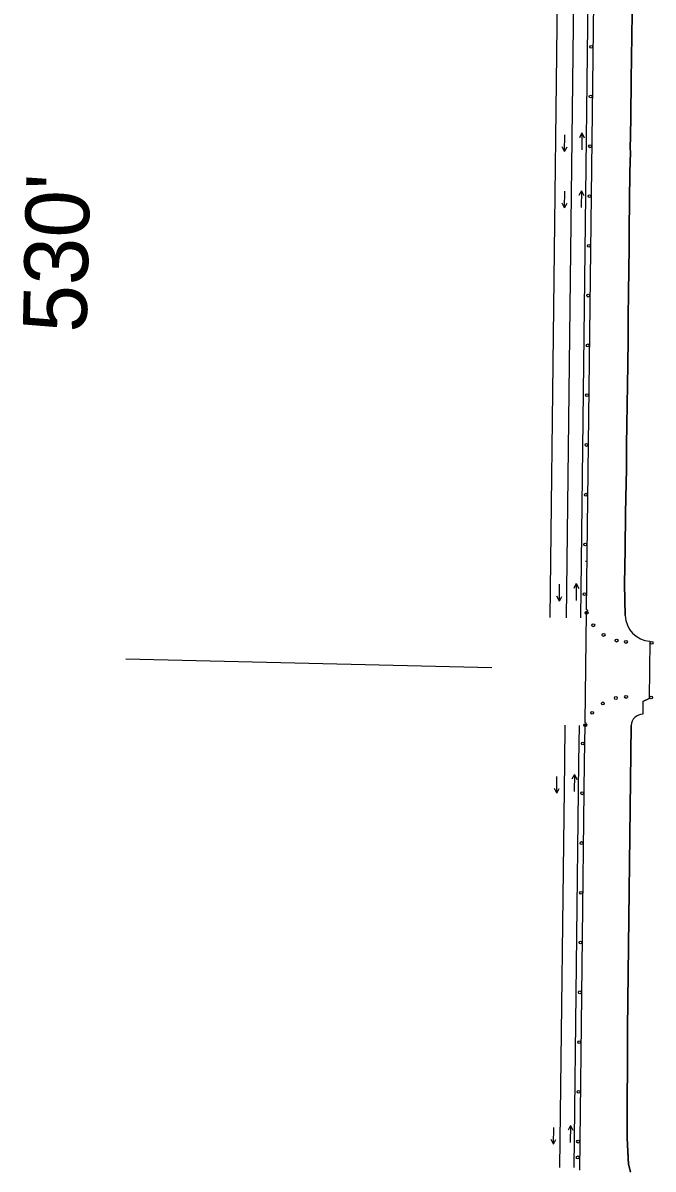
# Model space of a CAD drawing. Extents: x 1650647 to 1653016, y 602856 to 611467.
# Drawn here: x 1652157 to 1652600, y 606913 to 607719 of the extents above; entities that cross this region are included whole.
import ezdxf

# ---------------------------------------------------------------- set-up
doc = ezdxf.new("R2010")
doc.units = 0
for name, color, linetype in [('CM_Corridor_Design', 7, 'Continuous'), ('DT_X_Break_Line', 7, 'Continuous'), ('DT_X_Contour_Major', 7, 'Continuous'), ('PV_P_EOP', 7, 'Continuous'), ('PV_X_EOP', 7, 'Continuous'), ('SC_Scratch1', 7, 'Continuous'), ('UT_X_Water', 7, 'Continuous')]:
    doc.layers.add(name, color=color, linetype=linetype)

msp = doc.modelspace()

# ---------------------------------------------------------------- linework, layer by layer
at = {"layer": 'CM_Corridor_Design'}
for p, q in [((1652549.84, 607641.96), (1652548.08, 607638.6)), ((1652549.84, 607641.96), (1652549.71, 607630.1)), ((1652549.84, 607641.96), (1652551.52, 607638.57)), ((1652537.69, 607628.82), (1652537.82, 607640.68)), ((1652537.69, 607628.82), (1652536.01, 607632.22)), ((1652537.69, 607628.82), (1652539.45, 607632.18)), ((1652549.54, 607601.28), (1652547.78, 607597.92)), ((1652549.54, 607601.28), (1652549.41, 607589.42)), ((1652549.54, 607601.28), (1652551.23, 607597.89)), ((1652537.66, 607589.19), (1652537.79, 607601.05)), ((1652537.66, 607589.19), (1652535.97, 607592.59)), ((1652537.66, 607589.19), (1652539.42, 607592.55)), ((1652533.98, 607312.71), (1652534.11, 607324.57)), ((1652545.91, 607325.03), (1652544.15, 607321.68)), ((1652545.91, 607325.03), (1652545.78, 607313.18)), ((1652545.91, 607325.03), (1652547.6, 607321.64)), ((1652533.98, 607312.71), (1652532.29, 607316.1)), ((1652533.98, 607312.71), (1652535.74, 607316.07)), ((1652544.59, 607190.75), (1652542.83, 607187.4)), ((1652544.59, 607190.75), (1652544.46, 607178.9)), ((1652544.59, 607190.75), (1652546.27, 607187.36)), ((1652532.12, 607177.57), (1652532.25, 607189.43)), ((1652532.12, 607177.57), (1652530.44, 607180.96)), ((1652532.12, 607177.57), (1652533.88, 607180.93)), ((1652529.84, 606930.77), (1652529.97, 606942.63)), ((1652541.82, 606943.94), (1652540.06, 606940.59)), ((1652541.82, 606943.94), (1652541.69, 606932.08)), ((1652541.82, 606943.94), (1652543.51, 606940.55)), ((1652529.84, 606930.77), (1652528.15, 606934.17)), ((1652529.84, 606930.77), (1652531.6, 606934.13))]:
    msp.add_line(p, q, dxfattribs=at)
at = {"layer": 'DT_X_Break_Line'}
for centre in [(1652556.43, 607702.54), (1652556, 607667.55), (1652555.58, 607632.55), (1652555.16, 607597.55), (1652554.73, 607562.55), (1652554.31, 607527.56), (1652553.89, 607492.56), (1652553.46, 607457.56), (1652553.04, 607422.56), (1652552.62, 607387.57), (1652552.2, 607352.57), (1652551.73, 607317.55), (1652553.18, 607304.5), (1652557.85, 607295.71), (1652565.13, 607288.93), (1652574.24, 607284.91), (1652580.81, 607283.99), (1652598.9, 607283.39), (1652564.55, 607240.78), (1652573.75, 607244.58), (1652580.89, 607245.34), (1652598.48, 607244.95), (1652557.1, 607234.18), (1652552.23, 607225.5), (1652550.5, 607212.58), (1652550.08, 607177.58), (1652549.66, 607142.58), (1652549.23, 607107.59), (1652548.81, 607072.59), (1652548.38, 607037.59), (1652547.96, 607002.59), (1652547.54, 606967.6), (1652547.11, 606932.6), (1652546.89, 606921.52)]:
    msp.add_circle(centre, 1, dxfattribs=at)
at = {"layer": 'DT_X_Contour_Major'}
for p, q in [((1652552.1, 607227.39), (1652553.03, 607304.6)), ((1652597.66, 607284.55), (1652597.19, 607244.16)), ((1652592.66, 607242.21), (1652592.65, 607233.13)), ((1652592.66, 607242.21), (1652597.19, 607244.16)), ((1652581.98, 607011.99), (1652584.56, 607225.23)), ((1652584.07, 606911.22), (1652582.56, 606916.81))]:
    msp.add_line(p, q, dxfattribs=at)
for points in [[(1652553.06, 607306.57), (1652569.14, 608647.46)], [(1652580.36, 607302.56), (1652579.83, 607324.71), (1652580.32, 607349.32), (1652580.53, 607374.27), (1652580.68, 607385.24), (1652581.17, 607405.6), (1652581.23, 607422.45), (1652581.52, 607436.71), (1652582.06, 607478.93), (1652582.29, 607496.85), (1652582.4, 607512.31), (1652582.59, 607529.76), (1652583.14, 607561.47), (1652583.15, 607574.29), (1652583.59, 607614.17), (1652583.92, 607628.38), (1652583.8, 607631.29), (1652583.98, 607639.93), (1652584.18, 607653.35), (1652584.49, 607679.21), (1652585.3, 607725.82)], [(1652585.3, 607725.82), (1652584.49, 607679.21), (1652584.18, 607653.35), (1652583.98, 607639.93), (1652583.8, 607631.29), (1652583.92, 607628.38), (1652583.59, 607614.17), (1652583.15, 607574.29), (1652583.14, 607561.47), (1652582.59, 607529.76), (1652582.4, 607512.31), (1652582.29, 607496.85), (1652582.06, 607478.93), (1652581.52, 607436.71), (1652581.23, 607422.45), (1652581.17, 607405.6), (1652580.68, 607385.24), (1652580.53, 607374.27), (1652580.32, 607349.32), (1652579.83, 607324.71), (1652580.36, 607302.56)], [(1652597.66, 607284.55), (1652597.19, 607244.16), (1652592.66, 607242.21), (1652592.65, 607233.13)], [(1652548.28, 606912.42), (1652551.76, 607199.34), (1652552.08, 607225.41)], [(1652584.56, 607225.23), (1652581.98, 607012.02), (1652581.98, 607012.04), (1652581.98, 607011.99), (1652581.98, 607012.02), (1652581.7, 606935.13), (1652582.59, 606916.7), (1652582.56, 606916.81), (1652582.6, 606916.6), (1652582.59, 606916.7), (1652584.01, 606911.43)], [(1652582.6, 606916.6), (1652581.7, 606935.13), (1652581.98, 607012.04)]]:
    msp.add_lwpolyline(points, dxfattribs=at)
for centre, radius, start, end in [((1652552.89, 607305.59), 1, 278.00943, 80.60586), ((1652598.86, 607303.01), 18.5, 181.38515, 266.28371), ((1652598.86, 607303.01), 18.5, 181.38515, 266.28371), ((1652592.56, 607225.13), 8, 89.32859, 179.30691), ((1652592.56, 607225.13), 8, 89.32859, 179.30691), ((1652551.94, 607226.4), 1, 278.00943, 80.60586)]:
    msp.add_arc(centre, radius, start, end, dxfattribs=at)
at = {"layer": 'PV_P_EOP'}
for p, q in [((1652548.99, 607300.94), (1652565.26, 608647.72)), ((1652553.47, 607340.68), (1652552.27, 607340.69)), ((1652547.76, 607199.39), (1652548.07, 607225.35)), ((1652544.31, 606914.32), (1652547.76, 607199.39))]:
    msp.add_line(p, q, dxfattribs=at)
at = {"layer": 'PV_X_EOP'}
for p, q in [((1652538.99, 607301.06), (1652555.27, 608648.04)), ((1652537.76, 607199.51), (1652538.07, 607225.47)), ((1652534.31, 606914.44), (1652537.76, 607199.51))]:
    msp.add_line(p, q, dxfattribs=at)
at = {"layer": 'SC_Scratch1'}
msp.add_line((1652527.49, 607301.2), (1652543.76, 608647.26), dxfattribs=at)
at = {"layer": 'UT_X_Water'}
msp.add_line((1652486.44, 607265.87), (1652228.96, 607271.84), dxfattribs=at)

# ---------------------------------------------------------------- texts
msp.add_text("530'", height=44.8, rotation=88.67201, dxfattribs=at).set_placement((1652201.3, 607501.29))

doc.saveas('drawing.dxf')
